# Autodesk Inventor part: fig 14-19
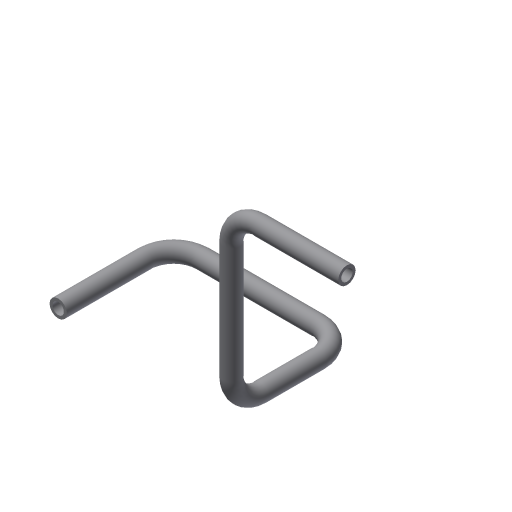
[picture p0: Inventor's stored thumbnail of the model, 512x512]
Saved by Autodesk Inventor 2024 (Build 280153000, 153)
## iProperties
Created: 2005-03
Part Number: fig 14-19
Document SubType Name: Modeling
Designer: CADCIM
Manufacturer: Standard
Standards Organization: Custom
Density: 1 g/cm^3
Material: Generic
Appearance: Default
Author: CADCIM
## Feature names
1. Sweep1
## Parameters: d9 = 6 mm, d10 = 4 mm, d11 = 0, d12 = 0
